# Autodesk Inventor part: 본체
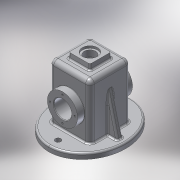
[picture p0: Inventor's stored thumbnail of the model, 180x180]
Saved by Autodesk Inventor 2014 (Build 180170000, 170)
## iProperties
Created: 2017-07
Part Number: 본체
Material: 알루미늄 6061
Document SubType Name: Modeling
Designer: user
Density: 2.71001 g/cm^3
Appearance: 알루미늄 - 평지
Mass: 895 g
Surface Area: 993.065 cm^2
Volume: 330.256 cm^3
Author: user
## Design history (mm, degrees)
sketch "스케치1"
  geometry: L1 (0, 0)-(75, 0); L2 (0, 0)-(-75, 0); L3 (0, 0)-(0, 65); L4 (0, 0)-(0, -65); 1 further point; 1 other entity
  constraints: 8 end point, 2 collinear, 1 coincident, 1 horizontal, 1 perpendicular, 1 vertical, 4 other
  dimensions: "d0" = 75 distance of L1.start L1.end; "d1" = 75 distance of L1.start L2.end; "d2" = 65 distance of L1.start L3.end; "d3" = 65 distance of L1.start L4.end
extrude "돌출1" new body sketch "스케치1" distance "d4" = 10; taper "d5" = 0 deg
sketch "스케치2"
  geometry: L1 (37, -37)-(-37, -37); L2 (-37, -37)-(-37, 37); L3 (-37, 37)-(37, 37); L4 (37, 37)-(37, -37); L5 (37, -37)-(-37, 37); L6 (-37, -37)-(37, 37); 1 further point
  constraints: 12 end point, 2 midpoint, 2 parallel, 1 horizontal, 1 perpendicular
  dimensions: "d6" = 74 distance of L2.end L3.end; "d7" = 74 distance of L1.end L2.end
extrude "돌출2" join sketch "스케치2" distance "d8" = 100; taper "d9" = 0 deg
sketch "스케치3"
  geometry: L1 (32, -32)-(-32, -32); L2 (-32, -32)-(-32, 32); L3 (-32, 32)-(32, 32); L4 (32, 32)-(32, -32); L5 (32, -32)-(-32, 32); L6 (-32, -32)-(32, 32); 1 further point
  constraints: 12 end point, 2 midpoint, 2 parallel, 1 horizontal, 1 perpendicular
  dimensions: "d10" = 64 distance of L2.end L3.end; "d11" = 64 distance of L1.end L2.end
extrude "돌출3" cut sketch "스케치3" distance "d12" = 105; taper "d13" = 0 deg
sketch "스케치4"
  geometry: L1 (10, -65)-(10, 65) reference; L2 (10, 55)-(88.894, 35.329); L3 (10, 55)-(91.31, 55); L4 (88.894, 35.329)-(10, 35.329); L5 (10, 55)-(10, 35.329); 1 further point
  constraints: 8 end point, 2 point on line, 1 collinear, 1 equal length, 1 horizontal, 1 perpendicular
  dimensions: "d14" = 14 deg angle of L2 L3; "d15" = 10 distance of L1.end L2.start
extrude "돌출4" join sketch "스케치4" stored distance "d16" = 10; taper "d17" = 0 deg
sketch "스케치5"
  geometry: L1 (0, 55)-(-50, 55); L2 (-50, 55)-(-50, 82.5); L3 (-32, 0)-(-32, 105) reference; L4 (-50, 82.5)-(-32, 82.5); L5 (-32, 82.5)-(-25, 75.5); L6 (-32, 82.5)-(-22.101, 82.5); L7 (-25, 75.5)-(-25, 55); L8 (-25, 71)-(-50, 71); 1 further point
  constraints: 14 end point, 3 perpendicular, 3 point on line, 2 horizontal, 1 equal length, 1 midpoint
  dimensions: "d18" = 50 distance of L1.start L1.end; "d19" = 55 distance from line of point (0, 0) L1; "d20" = 45 deg angle of L5 L6; "d21" = 7 distance from line of L3 L5.end; "d22" = 32 diameter of L8 L1; "d23" = 55 diameter of L4 L1
revolve "회전1" sketch "스케치5" stored, may be unused: angle "d24" = 90 deg
sketch "스케치6"
  geometry: C1 r 16 at (0, 0); 1 further point
  constraints: 1 centre point
  dimensions: "d25" = 32 diameter of C1
extrude "돌출5" cut sketch "스케치6" stored distance "d26" = 10; taper "d27" = 0 deg
sketch "스케치7"
  geometry: L1 (-20, -20)-(20, -20); L2 (20, -20)-(20, 20); L3 (20, 20)-(-20, 20); L4 (-20, 20)-(-20, -20); L5 (-20, -20)-(20, 20); L6 (20, -20)-(-20, 20); 1 further point
  constraints: 12 end point, 2 midpoint, 2 parallel, 1 horizontal, 1 perpendicular
  dimensions: "d28" = 40 distance of L3.end L2.end; "d29" = 40 distance of L2.end L1.end
extrude "돌출6" join sketch "스케치7" distance "d30" = 10; taper "d31" = 0 deg
sketch "스케치8"
  geometry: 2 further points
  constraints: 1 coincident
hole "구멍1" sketch "스케치8" at (0, 0) diameter "d32" = 21; stored, may be unused: countersink angle "d36" = 90 deg, drill point angle "d38" = 118 deg; dims "d33" = 6, "d34" = 28, "d35" = 4, "d37" = 8
chamfer "모따기1" distance "d39" = 10; stored, may be unused: second distance "d40" = 2, angle "d41" = 5 deg
chamfer "모따기2" distance "d42" = 10; stored, may be unused: second distance "d43" = 2, angle "d44" = 5 deg
chamfer "모따기3" distance "d45" = 10; stored, may be unused: second distance "d46" = 2, angle "d47" = 5 deg
chamfer "모따기4" distance "d48" = 10; stored, may be unused: second distance "d49" = 2, angle "d50" = 5 deg
sketch "스케치9" dims "d51" = 45
  geometry: 4 further points
  constraints: 1 coincident, 1 vertical alignment, 2 other
hole "구멍2" sketch "스케치9" at (0, 22.5) diameter "d52" = 3.242; stored, may be unused: countersink angle "d56" = 90 deg, drill point angle "d58" = 118 deg; dims "d53" = 8, "d54" = 28, "d55" = 4, "d57" = 10
sketch "스케치10"
  geometry: 3 further points
  dimensions: "d62" = 116 distance of point (58, 0) point (-58, 0); "d63" = 58 distance of point (0, 0) point (-58, 0)
hole "구멍3" sketch "스케치10" at (-58, 0), (58, 0) diameter "d64" = 10; stored, may be unused: countersink angle "d68" = 90 deg, drill point angle "d70" = 118 deg; dims "d65" = 8, "d66" = 28, "d67" = 4, "d69" = 10
fillet "모깎기1" dims "d71" = 0.5
fillet "모깎기2" dims "d72" = 8
fillet "모깎기3" dims "d73" = 8
fillet "모깎기4" dims "d74" = 3
fillet "모깎기5" dims "d75" = 3
fillet "모깎기8" dims "d78" = 3
fillet "모깎기9" dims "d79" = 3
fillet "모깎기10" dims "d80" = 3
fillet "모깎기11" dims "d81" = 3
fillet "모깎기12" dims "d82" = 3
chamfer "모따기5" distance "d83" = 1; stored, may be unused: second distance "d84" = 2, angle "d85" = 5 deg
node "작업 평면1"
sketch "스케치11"
  geometry: L1 (45.137, 18)-(12.863, 18) reference; L2 (66, -89)-(66, 0) reference; 2 further points
  constraints: 1 other
  dimensions: "d87" = 30 distance from line of L1 point (29, -12); "d88" = 37 distance from line of L2 point (29, -12)
feature "엠보싱1" sketch "스케치11" dims "d0" = 75, "d1" = 75, "d2" = 65, "d3" = 65, "d10" = 64, "d11" = 64, "d89" = 0.5, "d90" = 0
fillet "모깎기13" dims "d91" = 0.5
fillet "모깎기14" dims "d92" = 3
node "솔리드1"
mirror "대칭1"
mirror "대칭2"
pattern_circular "원형 패턴1" dims angle "d60" = 360 deg
mirror "대칭3"
other parameters: "d86" = 5
